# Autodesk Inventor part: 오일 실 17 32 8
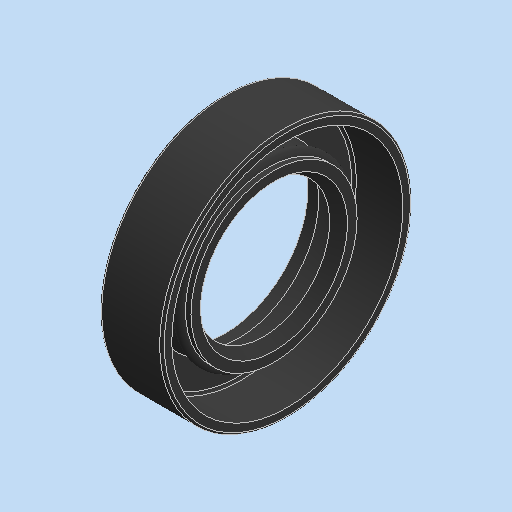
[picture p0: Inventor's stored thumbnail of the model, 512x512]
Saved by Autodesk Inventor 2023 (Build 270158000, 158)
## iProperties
Created: 2026-04
Part Number: 오일 실 17 32 8
Material: 고무
Description: 오일-실
Document SubType Name: Modeling
Designer: home
Density: 0.93 g/cm^3
Appearance: 기본값
Author: jhkim
Sending System: Autodesk Inventor 2027
Preprocessor: ST-DEVELOPER v20.1
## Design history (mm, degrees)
feature "Solid1"
node "솔리드1"
